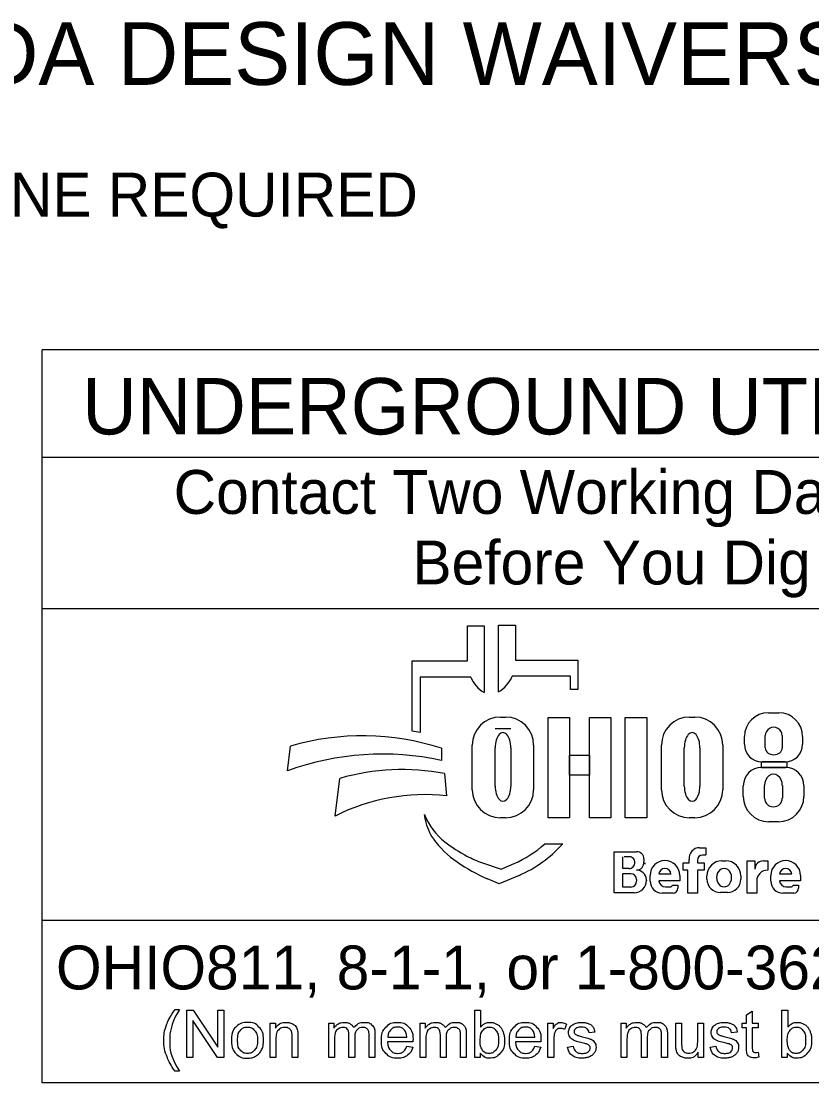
# Model space of a CAD drawing. Extents: x 36.7 to 70.7, y 0 to 22.
# Drawn here: x 39.005 to 41.525, y 2.14 to 5.526 of the extents above; entities that cross this region are included whole.
import ezdxf

# ---------------------------------------------------------------- set-up
doc = ezdxf.new("R2010")
doc.units = 0
doc.layers.add('SH_Data', color=7, linetype='Continuous')
doc.layers.add('SH_Text', color=7, linetype='Continuous')

msp = doc.modelspace()

# ---------------------------------------------------------------- linework, layer by layer
at = {"layer": 'SH_Data'}
for p, q in [((39.0709, 2.1397), (39.0709, 4.4772)), ((43.3209, 4.4772), (39.0709, 4.4772)), ((39.0709, 4.1356), (43.3209, 4.1356)), ((39.0709, 3.6522), (43.3209, 3.6522)), ((43.3209, 2.6576), (39.0709, 2.6576)), ((43.3209, 2.1397), (39.0709, 2.1397))]:
    msp.add_line(p, q, dxfattribs=at)
at = {"layer": 'SH_Text'}
for p, q in [((40.427, 3.4852), (40.427, 3.5967)), ((40.427, 3.5967), (40.4806, 3.5967)), ((40.4806, 3.5967), (40.4806, 3.3846)), ((40.5263, 3.387), (40.5263, 3.599)), ((40.5263, 3.599), (40.5799, 3.599)), ((40.5799, 3.599), (40.5799, 3.4875)), ((40.5799, 3.4875), (40.7792, 3.4875)), ((40.7792, 3.4875), (40.7792, 3.3937)), ((40.251, 3.2613), (40.251, 3.4852)), ((40.251, 3.4852), (40.427, 3.4852)), ((40.2762, 3.4338), (40.2762, 3.2569)), ((40.4374, 3.4338), (40.2762, 3.4338)), ((40.7559, 3.4361), (40.5695, 3.4361)), ((40.7559, 3.3937), (40.7559, 3.4361)), ((40.7792, 3.3937), (40.7559, 3.3937)), ((41.3865, 3.32), (41.4193, 3.32)), ((40.5319, 3.306), (40.5485, 3.306)), ((41.135, 3.306), (41.1515, 3.306)), ((40.5652, 3.269), (40.5154, 3.269)), ((40.4425, 3.0745), (40.4425, 3.2166)), ((40.638, 3.2166), (40.638, 3.0745)), ((41.0455, 3.0745), (41.0455, 3.2166)), ((41.241, 3.2166), (41.241, 3.0745)), ((41.3102, 3.2194), (41.3102, 3.2437)), ((41.3764, 3.208), (41.3764, 3.2473)), ((41.4305, 3.2473), (41.4305, 3.208)), ((41.4956, 3.2437), (41.4956, 3.2194)), ((39.8536, 3.135), (39.863, 3.2132)), ((40.3443, 3.2067), (40.3443, 3.1678)), ((40.5154, 3.0859), (40.5154, 3.2083)), ((40.5652, 3.2083), (40.5652, 3.0859)), ((41.1184, 3.0859), (41.1184, 3.2083)), ((41.1682, 3.2083), (41.1682, 3.0859)), ((41.4396, 3.1634), (41.3662, 3.1634)), ((40.3543, 3.1261), (40.3605, 3.0551)), ((41.3644, 3.1451), (41.4417, 3.1451)), ((40.0055, 2.9905), (40.0201, 3.1106)), ((41.3065, 3.0532), (41.3065, 3.0872)), ((41.374, 3.0472), (41.374, 3.0882)), ((41.4309, 3.0882), (41.4309, 3.0472)), ((41.4996, 3.0872), (41.4996, 3.0532)), ((40.2931, 2.9776), (40.2901, 2.9955)), ((40.5485, 2.9851), (40.5319, 2.9851)), ((41.1515, 2.9851), (41.135, 2.9851)), ((41.4187, 2.9722), (41.3875, 2.9722)), ((40.6734, 2.9017), (40.7309, 2.9017)), ((41.1673, 2.8895), (41.1868, 2.8895)), ((41.1868, 2.8895), (41.1868, 2.8665)), ((40.8947, 2.746), (40.8947, 2.8767)), ((40.8947, 2.8767), (40.9659, 2.8767)), ((40.9227, 2.8232), (40.9227, 2.8601)), ((40.9479, 2.8601), (40.9266, 2.8601)), ((40.9897, 2.8529), (40.9897, 2.845)), ((41.134, 2.8411), (41.134, 2.8515)), ((41.1601, 2.8495), (41.1601, 2.8411)), ((41.1868, 2.866), (41.1766, 2.866)), ((41.2385, 2.8477), (41.2507, 2.8477)), ((41.3188, 2.7448), (41.3188, 2.8475)), ((41.3188, 2.8475), (41.3433, 2.8475)), ((41.3433, 2.8475), (41.3433, 2.8206)), ((41.3706, 2.8475), (41.3845, 2.8475)), ((41.3845, 2.8475), (41.3845, 2.8178)), ((40.475, 2.8413), (40.5344, 2.8209)), ((40.5344, 2.8209), (40.5755, 2.8387)), ((40.9421, 2.8232), (40.9227, 2.8232)), ((41.1147, 2.8181), (41.1147, 2.8411)), ((41.1147, 2.8411), (41.134, 2.8411)), ((41.1296, 2.8181), (41.1147, 2.8181)), ((41.1296, 2.7448), (41.1296, 2.8181)), ((41.1601, 2.8411), (41.1817, 2.8411)), ((41.1817, 2.8181), (41.1601, 2.8181)), ((41.1601, 2.8181), (41.1601, 2.7448)), ((41.1817, 2.8411), (41.1817, 2.8181)), ((40.5284, 2.7738), (40.4911, 2.7903)), ((40.5917, 2.8013), (40.5284, 2.7738)), ((40.9227, 2.7638), (40.9227, 2.8067)), ((40.9227, 2.8067), (40.9482, 2.8067)), ((40.9664, 2.7885), (40.9664, 2.7822)), ((40.9977, 2.7856), (40.9977, 2.7853)), ((41.0093, 2.7827), (41.0093, 2.8012)), ((41.0759, 2.8051), (41.0373, 2.8051)), ((41.1038, 2.7835), (41.0374, 2.7835)), ((41.1038, 2.8012), (41.1038, 2.7835)), ((41.1907, 2.7891), (41.1907, 2.7999)), ((41.2985, 2.7999), (41.2985, 2.7891)), ((41.3493, 2.7829), (41.3493, 2.7448)), ((41.3942, 2.7827), (41.3942, 2.8012)), ((41.4608, 2.8051), (41.4223, 2.8051)), ((41.4887, 2.7835), (41.4223, 2.7835)), ((41.4887, 2.8012), (41.4887, 2.7835)), ((40.9584, 2.746), (40.8947, 2.746)), ((40.948, 2.7638), (40.9227, 2.7638)), ((41.0826, 2.7448), (41.0473, 2.7448)), ((41.0583, 2.7642), (41.0724, 2.7642)), ((41.081, 2.7698), (41.0979, 2.7698)), ((41.0979, 2.7698), (41.0979, 2.76)), ((41.1601, 2.7448), (41.1296, 2.7448)), ((41.2557, 2.7463), (41.2335, 2.7463)), ((41.3493, 2.7448), (41.3188, 2.7448)), ((41.4676, 2.7448), (41.4322, 2.7448)), ((41.4432, 2.7642), (41.4574, 2.7642)), ((41.4659, 2.7698), (41.4828, 2.7698)), ((41.4828, 2.7698), (41.4828, 2.76))]:
    msp.add_line(p, q, dxfattribs=at)
for points in [[(40.6844, 3.305), (40.7523, 3.305), (40.7523, 2.985), (40.6844, 2.985)], [(40.8165, 3.305), (40.8845, 3.305), (40.8845, 2.985), (40.8165, 2.985)], [(40.9298, 3.305), (40.9986, 3.305), (40.9986, 2.985), (40.9298, 2.985)], [(40.7523, 3.1851), (40.8165, 3.1851), (40.8165, 3.1211), (40.7523, 3.1211)], [(41.3641, 3.1635), (41.4457, 3.1635), (41.4457, 3.145), (41.3641, 3.145)]]:
    msp.add_lwpolyline(points, close=True, dxfattribs=at)
for points in [[(39.4955, 2.3735), (39.5087, 2.3735)], [(39.5323, 2.2208), (39.5323, 2.371), (39.5526, 2.371), (39.6316, 2.2531), (39.6316, 2.371), (39.6506, 2.371), (39.6506, 2.2208), (39.6303, 2.2208), (39.5513, 2.3388), (39.5513, 2.2208), (39.5323, 2.2208)], [(40.4677, 2.2208), (40.4507, 2.2208), (40.4507, 2.371), (40.4691, 2.371), (40.4691, 2.3175)], [(41.4468, 2.2208), (41.4298, 2.2208), (41.4298, 2.371), (41.4482, 2.371), (41.4482, 2.3175)], [(41.3167, 2.2527), (41.3167, 2.3154), (41.3031, 2.3154), (41.3031, 2.3297), (41.3167, 2.3297), (41.3167, 2.3566), (41.3351, 2.3677), (41.3351, 2.3297), (41.3535, 2.3297), (41.3535, 2.3154), (41.3351, 2.3154), (41.3351, 2.2516)], [(39.7982, 2.2208), (39.7982, 2.3297), (39.8148, 2.3297), (39.8148, 2.3142)], [(39.9847, 2.2208), (39.9847, 2.3297), (40.0011, 2.3297), (40.0011, 2.3143)], [(40.276, 2.2208), (40.276, 2.3297), (40.2925, 2.3297), (40.2925, 2.3143)], [(40.6838, 2.2208), (40.6838, 2.3297), (40.7004, 2.3297), (40.7004, 2.3132)], [(40.7429, 2.3262), (40.7364, 2.3091)], [(40.917, 2.2208), (40.917, 2.3297), (40.9335, 2.3297), (40.9335, 2.3143)], [(41.0913, 2.2623), (41.0913, 2.3297), (41.1098, 2.3297), (41.1098, 2.2694)], [(41.161, 2.2714), (41.161, 2.3297), (41.1795, 2.3297), (41.1795, 2.2208), (41.163, 2.2208)], [(39.8167, 2.2802), (39.8167, 2.2208), (39.7982, 2.2208)], [(39.8866, 2.2877), (39.8866, 2.2208), (39.8682, 2.2208), (39.8682, 2.287)], [(40.0031, 2.2773), (40.0031, 2.2208), (39.9847, 2.2208)], [(40.0677, 2.284), (40.0677, 2.2208), (40.0493, 2.2208), (40.0493, 2.2915)], [(40.1322, 2.2955), (40.1322, 2.2208), (40.1137, 2.2208), (40.1137, 2.2893)], [(40.2534, 2.2705), (40.1722, 2.2705)], [(40.1733, 2.2856), (40.234, 2.2856)], [(40.2945, 2.2773), (40.2945, 2.2208), (40.276, 2.2208)], [(40.3591, 2.284), (40.3591, 2.2208), (40.3407, 2.2208), (40.3407, 2.2915)], [(40.4235, 2.2955), (40.4235, 2.2208), (40.4051, 2.2208), (40.4051, 2.2893)], [(40.6614, 2.2705), (40.5802, 2.2705)], [(40.5813, 2.2856), (40.642, 2.2856)], [(40.7022, 2.2778), (40.7022, 2.2208), (40.6838, 2.2208)], [(40.8328, 2.3015), (40.8147, 2.2991)], [(40.9355, 2.2773), (40.9355, 2.2208), (40.917, 2.2208)], [(41.0001, 2.284), (41.0001, 2.2208), (40.9817, 2.2208), (40.9817, 2.2915)], [(41.0645, 2.2955), (41.0645, 2.2208), (41.0461, 2.2208), (41.0461, 2.2893)], [(41.2874, 2.3015), (41.2693, 2.2991)], [(40.2338, 2.256), (40.2529, 2.2536)], [(40.6418, 2.256), (40.6609, 2.2536)], [(40.7464, 2.2533), (40.7646, 2.2562)], [(41.163, 2.2208), (41.163, 2.2369)], [(41.201, 2.2533), (41.2192, 2.2562)], [(41.3535, 2.2373), (41.3562, 2.221)], [(40.4677, 2.2345), (40.4677, 2.2208)], [(41.4468, 2.2345), (41.4468, 2.2208)], [(39.5087, 2.1767), (39.4955, 2.1767)]]:
    msp.add_lwpolyline(points, dxfattribs=at)
for centre, radius, start, end in [((40.5287, 3.4705), 0.0985, 201.9296, 240.7469), ((40.4781, 3.4729), 0.0985, 299.2531, 338.0704), ((41.3865, 3.2437), 0.0763, 90, 180), ((41.4193, 3.2437), 0.0763, 0, 90), ((40.5319, 3.2166), 0.0895, 90, 180), ((40.5485, 3.2166), 0.0895, 0, 90), ((41.135, 3.2166), 0.0895, 90, 180), ((41.1515, 3.2166), 0.0895, 0, 90), ((40.1229, 2.4523), 0.8191, 79.2074, 81.0007), ((40.0931, 2.4271), 0.8191, 72.1402, 106.3144), ((41.3662, 3.2194), 0.056, 180, 270), ((41.4396, 3.2194), 0.056, 270, 0), ((40.1562, 2.296), 0.8919, 77.8238, 109.8274), ((40.2201, 2.4063), 0.7322, 79.44, 105.8467), ((41.3644, 3.0872), 0.0579, 90, 180), ((41.4417, 3.0872), 0.0579, 0, 90), ((40.2921, 2.4231), 0.6357, 83.8248, 116.8021), ((40.5319, 3.0745), 0.0895, 180, 270), ((40.5485, 3.0745), 0.0895, 270, 0), ((41.135, 3.0745), 0.0895, 180, 270), ((41.1515, 3.0745), 0.0895, 270, 0), ((41.3875, 3.0532), 0.081, 180, 270), ((41.4187, 3.0532), 0.081, 270, 0), ((40.4775, 3.0676), 0.2008, 201.0457, 232.5314), ((40.4345, 3.0017), 0.1433, 189.6817, 216.0884), ((40.5681, 3.0991), 0.3088, 216.0884, 235.7167), ((40.67, 3.3188), 0.5173, 232.5314, 241.794), ((40.4321, 3.1691), 0.3602, 293.4582, 312.0712), ((40.4321, 3.1691), 0.401, 293.4582, 317.8286), ((41.1673, 2.8559), 0.0335, 90, 187.5187), ((40.5848, 3.16), 0.3371, 241.794, 250.9821), ((40.944, 2.8432), 0.0169, 357.8325, 90), ((40.9655, 2.8422), 0.0243, 270, 6.6529), ((40.9659, 2.8529), 0.0238, 0, 90), ((41.0565, 2.8012), 0.0473, 0, 180), ((41.1766, 2.8495), 0.0165, 90, 180), ((41.2385, 2.7999), 0.0478, 90, 180), ((41.2507, 2.7999), 0.0478, 0, 90), ((41.3702, 2.8206), 0.0269, 89.2449, 180), ((41.4415, 2.8012), 0.0473, 0, 180), ((40.7346, 3.3434), 0.6044, 235.7167, 246.2325), ((40.9421, 2.8419), 0.0187, 270, 2.0582), ((40.9656, 2.7858), 0.0321, 4.0748, 90), ((40.9761, 2.8407), 0.0175, 347.4023, 0), ((41.0566, 2.8041), 0.0193, 2.9632, 177.0368), ((41.3842, 2.7829), 0.0349, 89.6033, 180), ((41.4415, 2.8041), 0.0193, 2.9632, 177.0368), ((40.948, 2.7822), 0.0184, 270, 0), ((40.9482, 2.7885), 0.0181, 0, 90), ((40.9584, 2.7853), 0.0393, 270, 0), ((40.9648, 2.7856), 0.033, 0, 11.7502), ((41.0473, 2.7827), 0.038, 180, 270), ((41.0583, 2.7853), 0.021, 184.827, 270), ((41.2335, 2.7891), 0.0428, 180, 270), ((41.2557, 2.7891), 0.0428, 270, 0), ((41.4322, 2.7827), 0.038, 180, 270), ((41.4432, 2.7853), 0.021, 184.827, 270), ((41.0724, 2.7736), 0.00938, 270, 335.9979), ((41.0826, 2.76), 0.0152, 270, 0), ((41.4574, 2.7736), 0.00938, 270, 335.9979), ((41.4676, 2.76), 0.0152, 270, 0)]:
    msp.add_arc(centre, radius, start, end, dxfattribs=at)
for centre, major_axis, ratio, start_param, end_param in [((40.5403, 3.2083), (0, 0.0484), 0.514403, 4.712389, 7.853982), ((41.1433, 3.2083), (0, 0.0484), 0.514403, 4.712389, 7.853982), ((41.4034, 3.2473), (0.0271, 0), 0.969373, 0, 3.141593), ((41.4034, 3.208), (0.0271, 0), 0.818453, 3.141593, 6.283185), ((41.4024, 3.0882), (0, 0.0358), 0.794529, 4.712389, 7.853982), ((40.5403, 3.0859), (0, 0.0484), 0.514403, 1.570796, 4.712389), ((41.1433, 3.0859), (0, 0.0484), 0.514403, 1.570796, 4.712389), ((41.4024, 3.0472), (0.0284, 0), 0.959837, 3.141593, 6.283185), ((41.2451, 2.7945), (0, 0.029), 0.832186, 4.712389, 7.853982), ((41.2451, 2.7945), (0, 0.0302), 0.797287, 1.570796, 4.712389)]:
    msp.add_ellipse(centre, major_axis=major_axis, ratio=ratio, start_param=start_param, end_param=end_param, dxfattribs=at)
for points in [[(39.4955, 2.1767), (39.4803, 2.1959), (39.4697, 2.2217), (39.4592, 2.2475), (39.4592, 2.2752), (39.4592, 2.2996), (39.467, 2.3219), (39.4763, 2.3478), (39.4955, 2.3735)], [(39.5087, 2.3735), (39.4963, 2.3522), (39.4924, 2.3431), (39.4861, 2.329), (39.4825, 2.3136), (39.4781, 2.2944), (39.4781, 2.2751), (39.4781, 2.2258), (39.5087, 2.1767)], [(39.6748, 2.2753), (39.6748, 2.3055), (39.6916, 2.32), (39.7056, 2.3321), (39.7257, 2.3321), (39.7482, 2.3321), (39.7624, 2.3174), (39.7766, 2.3027), (39.7766, 2.2768), (39.7766, 2.2558), (39.7703, 2.2438), (39.764, 2.2317), (39.752, 2.2251), (39.74, 2.2184), (39.7257, 2.2184), (39.7029, 2.2184), (39.6888, 2.2331), (39.6748, 2.2477), (39.6748, 2.2753)], [(39.6938, 2.2753), (39.6938, 2.2543), (39.7029, 2.2439), (39.7119, 2.2335), (39.7257, 2.2335), (39.7394, 2.2335), (39.7485, 2.244), (39.7576, 2.2544), (39.7576, 2.2759), (39.7576, 2.2961), (39.7485, 2.3065), (39.7393, 2.3169), (39.7257, 2.3169), (39.7119, 2.3169), (39.7029, 2.3065), (39.6938, 2.2962), (39.6938, 2.2753)], [(39.8148, 2.3142), (39.8268, 2.3321), (39.8494, 2.3321), (39.8593, 2.3321), (39.8675, 2.3285), (39.8757, 2.325), (39.8798, 2.3193), (39.8839, 2.3135), (39.8856, 2.3057), (39.8866, 2.3005), (39.8866, 2.2877)], [(39.8682, 2.287), (39.8682, 2.2982), (39.866, 2.3038), (39.8639, 2.3094), (39.8584, 2.3127), (39.8529, 2.3161), (39.8455, 2.3161), (39.8338, 2.3161), (39.8252, 2.3086), (39.8167, 2.3011), (39.8167, 2.2802)], [(40.0011, 2.3143), (40.0063, 2.3223), (40.0148, 2.3272), (40.0233, 2.3321), (40.0341, 2.3321), (40.0462, 2.3321), (40.054, 2.327), (40.0617, 2.322), (40.0649, 2.313), (40.0778, 2.3321), (40.0985, 2.3321), (40.1147, 2.3321), (40.1235, 2.3231), (40.1322, 2.3142), (40.1322, 2.2955)], [(40.0493, 2.2915), (40.0493, 2.3038), (40.0448, 2.3099), (40.0403, 2.3161), (40.03, 2.3161), (40.0223, 2.3161), (40.0156, 2.312), (40.009, 2.3079), (40.0061, 2.3), (40.0031, 2.2921), (40.0031, 2.2773)], [(40.1137, 2.2893), (40.1137, 2.3004), (40.112, 2.3053), (40.1102, 2.3101), (40.1054, 2.3131), (40.1007, 2.3161), (40.0944, 2.3161), (40.0829, 2.3161), (40.0753, 2.3084), (40.0677, 2.3008), (40.0677, 2.284)], [(40.2529, 2.2536), (40.2484, 2.2369), (40.2362, 2.2277), (40.224, 2.2184), (40.2051, 2.2184), (40.1812, 2.2184), (40.1672, 2.2331), (40.1533, 2.2478), (40.1533, 2.2743), (40.1533, 2.3018), (40.1674, 2.3169), (40.1815, 2.3321), (40.204, 2.3321), (40.2259, 2.3321), (40.2397, 2.3172), (40.2535, 2.3024), (40.2535, 2.2754), (40.2535, 2.2738), (40.2534, 2.2705)], [(40.234, 2.2856), (40.2328, 2.2994), (40.2271, 2.3063), (40.2183, 2.317), (40.2042, 2.317), (40.1915, 2.317), (40.1829, 2.3084), (40.1742, 2.2999), (40.1733, 2.2856)], [(40.2925, 2.3143), (40.2976, 2.3223), (40.3061, 2.3272), (40.3146, 2.3321), (40.3255, 2.3321), (40.3376, 2.3321), (40.3453, 2.327), (40.3531, 2.322), (40.3562, 2.313), (40.3692, 2.3321), (40.3899, 2.3321), (40.4061, 2.3321), (40.4148, 2.3231), (40.4235, 2.3142), (40.4235, 2.2955)], [(40.3407, 2.2915), (40.3407, 2.3038), (40.3362, 2.3099), (40.3317, 2.3161), (40.3214, 2.3161), (40.3136, 2.3161), (40.307, 2.312), (40.3004, 2.3079), (40.2974, 2.3), (40.2945, 2.2921), (40.2945, 2.2773)], [(40.4051, 2.2893), (40.4051, 2.3004), (40.4033, 2.3053), (40.4015, 2.3101), (40.3968, 2.3131), (40.3921, 2.3161), (40.3858, 2.3161), (40.3743, 2.3161), (40.3667, 2.3084), (40.3591, 2.3008), (40.3591, 2.284)], [(40.4675, 2.2761), (40.4675, 2.2565), (40.4728, 2.2478), (40.4815, 2.2335), (40.4963, 2.2335), (40.5084, 2.2335), (40.5172, 2.244), (40.526, 2.2546), (40.526, 2.2754), (40.526, 2.2967), (40.5176, 2.3068), (40.5091, 2.317), (40.4972, 2.317), (40.4851, 2.317), (40.4763, 2.3065), (40.4675, 2.296), (40.4675, 2.2761)], [(40.4691, 2.3175), (40.4808, 2.3321), (40.4989, 2.3321), (40.5089, 2.3321), (40.5179, 2.328), (40.5269, 2.324), (40.5327, 2.3167), (40.5384, 2.3094), (40.5417, 2.299), (40.545, 2.2887), (40.545, 2.2769), (40.545, 2.2489), (40.5312, 2.2337), (40.5173, 2.2184), (40.498, 2.2184), (40.4787, 2.2184), (40.4677, 2.2345)], [(40.6609, 2.2536), (40.6564, 2.2369), (40.6442, 2.2277), (40.632, 2.2184), (40.6131, 2.2184), (40.5892, 2.2184), (40.5752, 2.2331), (40.5612, 2.2478), (40.5612, 2.2743), (40.5612, 2.3018), (40.5754, 2.3169), (40.5895, 2.3321), (40.612, 2.3321), (40.6338, 2.3321), (40.6477, 2.3172), (40.6615, 2.3024), (40.6615, 2.2754), (40.6615, 2.2738), (40.6614, 2.2705)], [(40.642, 2.2856), (40.6408, 2.2994), (40.6351, 2.3063), (40.6263, 2.317), (40.6122, 2.317), (40.5995, 2.317), (40.5909, 2.3084), (40.5822, 2.2999), (40.5813, 2.2856)], [(40.7004, 2.3132), (40.7067, 2.3247), (40.7121, 2.3284), (40.7175, 2.3321), (40.7239, 2.3321), (40.7332, 2.3321), (40.7429, 2.3262)], [(40.7364, 2.3091), (40.7297, 2.3131), (40.723, 2.3131), (40.7169, 2.3131), (40.7121, 2.3094), (40.7074, 2.3058), (40.7053, 2.2993), (40.7022, 2.2895), (40.7022, 2.2778)], [(40.8147, 2.2991), (40.8135, 2.3075), (40.8076, 2.3123), (40.8017, 2.317), (40.7909, 2.317), (40.7782, 2.317), (40.7728, 2.3128), (40.7674, 2.3086), (40.7674, 2.3029), (40.7674, 2.2993), (40.7696, 2.2965), (40.7719, 2.2935), (40.7767, 2.2915), (40.7795, 2.2905), (40.793, 2.2868), (40.8126, 2.2816), (40.8203, 2.2783), (40.8281, 2.2749), (40.8325, 2.2686), (40.8369, 2.2622), (40.8369, 2.2528), (40.8369, 2.2436), (40.8315, 2.2355), (40.8262, 2.2273), (40.816, 2.2229), (40.8058, 2.2184), (40.793, 2.2184), (40.7718, 2.2184), (40.7606, 2.2272), (40.7495, 2.236), (40.7464, 2.2533)], [(40.7646, 2.2562), (40.7662, 2.2452), (40.7732, 2.2394), (40.7802, 2.2335), (40.7929, 2.2335), (40.8056, 2.2335), (40.8118, 2.2387), (40.8179, 2.2439), (40.8179, 2.2509), (40.8179, 2.2571), (40.8125, 2.2607), (40.8087, 2.2632), (40.7936, 2.267), (40.7733, 2.2721), (40.7655, 2.2758), (40.7576, 2.2796), (40.7536, 2.2862), (40.7495, 2.2928), (40.7495, 2.3008), (40.7495, 2.308), (40.7528, 2.3142), (40.7562, 2.3204), (40.7619, 2.3245), (40.7662, 2.3277), (40.7737, 2.3299), (40.7811, 2.3321), (40.7896, 2.3321), (40.8024, 2.3321), (40.8121, 2.3284), (40.8218, 2.3247), (40.8265, 2.3184), (40.8311, 2.3121), (40.8328, 2.3015)], [(40.9335, 2.3143), (40.9386, 2.3223), (40.9471, 2.3272), (40.9556, 2.3321), (40.9665, 2.3321), (40.9786, 2.3321), (40.9863, 2.327), (40.9941, 2.322), (40.9972, 2.313), (41.0102, 2.3321), (41.0309, 2.3321), (41.0471, 2.3321), (41.0558, 2.3231), (41.0645, 2.3142), (41.0645, 2.2955)], [(40.9817, 2.2915), (40.9817, 2.3038), (40.9772, 2.3099), (40.9727, 2.3161), (40.9624, 2.3161), (40.9546, 2.3161), (40.948, 2.312), (40.9414, 2.3079), (40.9384, 2.3), (40.9355, 2.2921), (40.9355, 2.2773)], [(41.0461, 2.2893), (41.0461, 2.3004), (41.0443, 2.3053), (41.0425, 2.3101), (41.0378, 2.3131), (41.0331, 2.3161), (41.0268, 2.3161), (41.0153, 2.3161), (41.0077, 2.3084), (41.0001, 2.3008), (41.0001, 2.284)], [(41.2693, 2.2991), (41.2681, 2.3075), (41.2622, 2.3123), (41.2563, 2.317), (41.2455, 2.317), (41.2328, 2.317), (41.2274, 2.3128), (41.2219, 2.3086), (41.2219, 2.3029), (41.2219, 2.2993), (41.2242, 2.2965), (41.2264, 2.2935), (41.2313, 2.2915), (41.234, 2.2905), (41.2476, 2.2868), (41.2672, 2.2816), (41.2749, 2.2783), (41.2827, 2.2749), (41.2871, 2.2686), (41.2915, 2.2622), (41.2915, 2.2528), (41.2915, 2.2436), (41.2861, 2.2355), (41.2807, 2.2273), (41.2706, 2.2229), (41.2604, 2.2184), (41.2476, 2.2184), (41.2263, 2.2184), (41.2152, 2.2272), (41.2041, 2.236), (41.201, 2.2533)], [(41.2192, 2.2562), (41.2207, 2.2452), (41.2278, 2.2394), (41.2348, 2.2335), (41.2474, 2.2335), (41.2602, 2.2335), (41.2663, 2.2387), (41.2725, 2.2439), (41.2725, 2.2509), (41.2725, 2.2571), (41.2671, 2.2607), (41.2633, 2.2632), (41.2482, 2.267), (41.2279, 2.2721), (41.22, 2.2758), (41.2122, 2.2796), (41.2081, 2.2862), (41.2041, 2.2928), (41.2041, 2.3008), (41.2041, 2.308), (41.2074, 2.3142), (41.2107, 2.3204), (41.2165, 2.3245), (41.2208, 2.3277), (41.2282, 2.3299), (41.2357, 2.3321), (41.2442, 2.3321), (41.257, 2.3321), (41.2667, 2.3284), (41.2764, 2.3247), (41.281, 2.3184), (41.2856, 2.3121), (41.2874, 2.3015)], [(41.4466, 2.2761), (41.4466, 2.2565), (41.4519, 2.2478), (41.4606, 2.2335), (41.4754, 2.2335), (41.4875, 2.2335), (41.4963, 2.244), (41.5051, 2.2546), (41.5051, 2.2754), (41.5051, 2.2967), (41.4966, 2.3068), (41.4882, 2.317), (41.4762, 2.317), (41.4642, 2.317), (41.4554, 2.3065), (41.4466, 2.296), (41.4466, 2.2761)], [(41.4482, 2.3175), (41.4599, 2.3321), (41.478, 2.3321), (41.488, 2.3321), (41.497, 2.328), (41.5059, 2.324), (41.5117, 2.3167), (41.5175, 2.3094), (41.5208, 2.299), (41.5241, 2.2887), (41.5241, 2.2769), (41.5241, 2.2489), (41.5102, 2.2337), (41.4964, 2.2184), (41.477, 2.2184), (41.4578, 2.2184), (41.4468, 2.2345)], [(40.1722, 2.2705), (40.1733, 2.2526), (40.1824, 2.2431), (40.1915, 2.2335), (40.2051, 2.2335), (40.2153, 2.2335), (40.2225, 2.2389), (40.2296, 2.2442), (40.2338, 2.256)], [(40.5802, 2.2705), (40.5813, 2.2526), (40.5904, 2.2431), (40.5995, 2.2335), (40.6131, 2.2335), (40.6233, 2.2335), (40.6305, 2.2389), (40.6376, 2.2442), (40.6418, 2.256)], [(41.1098, 2.2694), (41.1098, 2.2549), (41.1109, 2.2499), (41.1126, 2.2426), (41.1183, 2.2385), (41.1239, 2.2343), (41.1322, 2.2343), (41.1405, 2.2343), (41.1477, 2.2386), (41.155, 2.2428), (41.158, 2.2502), (41.161, 2.2575), (41.161, 2.2714)], [(41.163, 2.2369), (41.1503, 2.2184), (41.1285, 2.2184), (41.1189, 2.2184), (41.1105, 2.2221), (41.1022, 2.2258), (41.0982, 2.2314), (41.0941, 2.237), (41.0925, 2.2451), (41.0913, 2.2505), (41.0913, 2.2623)], [(41.3562, 2.221), (41.3484, 2.2194), (41.3423, 2.2194), (41.3322, 2.2194), (41.3267, 2.2225), (41.3212, 2.2257), (41.3189, 2.2309), (41.3167, 2.2361), (41.3167, 2.2527)], [(41.3351, 2.2516), (41.3351, 2.2437), (41.3361, 2.2414), (41.337, 2.2392), (41.3392, 2.2379), (41.3414, 2.2365), (41.3455, 2.2365), (41.3485, 2.2365), (41.3535, 2.2373)]]:
    msp.add_open_spline(points, degree=3, dxfattribs=at)

# ---------------------------------------------------------------- texts
for s, height, p in [('ADA DESIGN WAIVERS', 0.2, (38.6878, 5.3225)), ('NONE REQUIRED', 0.14, (38.6878, 4.9025)), ('UNDERGROUND UTILITIES', 0.18, (39.1991, 4.2076)), ('Contact Two Working Days', 0.14, (39.4906, 3.9541)), ('Before You Dig', 0.14, (40.2517, 3.7291)), ('OHIO811, 8-1-1, or 1-800-362-2764', 0.14, (39.1154, 2.4375))]:
    msp.add_text(s, height=height, dxfattribs=at).set_placement(p)

doc.saveas('drawing.dxf')
